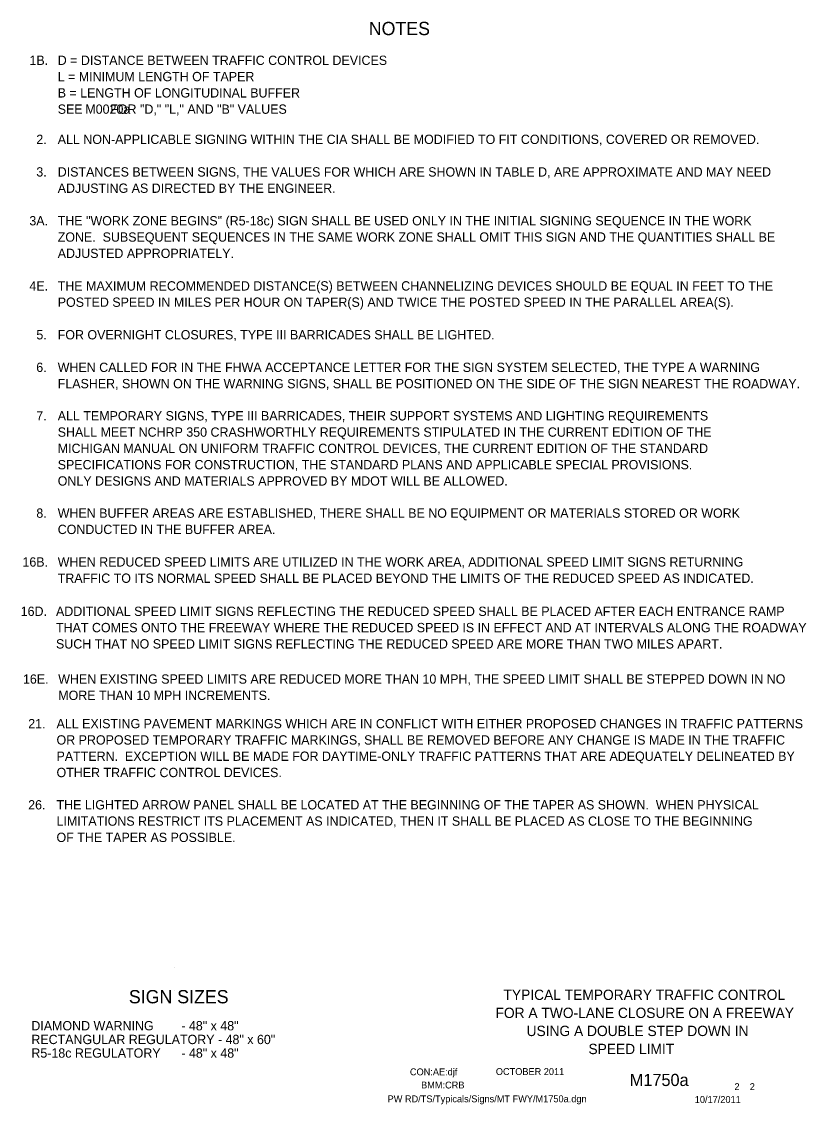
# Model space of a CAD drawing. Extents: x 16732 to 18478, y 5523 to 6928.
# Drawn here: x 17769 to 18478, y 5932 to 6909 of the extents above; entities that cross this region are included whole.
import ezdxf

# ---------------------------------------------------------------- set-up
doc = ezdxf.new("R2010")
doc.units = 0
for name, color, linetype in [('BORDER', 7, 'Continuous'), ('BORDER_SIGNAL_WO', 7, 'Continuous'), ('TYPICAL_TEXT_DIMEN_PR', 7, 'Continuous')]:
    doc.layers.add(name, color=color, linetype=linetype)

msp = doc.modelspace()

# ---------------------------------------------------------------- linework, layer by layer
at = {"layer": 'BORDER'}
for p, q in [((17907.48, 6055), (17907.48, 6055)), ((17907.48, 6035.02), (17907.48, 6035.02))]:
    msp.add_line(p, q, dxfattribs=at)

# ---------------------------------------------------------------- texts
for s, p in [('TYPICAL TEMPORARY TRAFFIC CONTROL', (18204.21, 6026.08)), ('FOR A TWO-LANE CLOSURE ON A FREEWAY', (18196.99, 6009.78)), ('USING A DOUBLE STEP DOWN IN', (18225.04, 5993.48)), ('SPEED LIMIT', (18280.92, 5977.18))]:
    msp.add_text(s, height=9.3, dxfattribs=at).set_placement(p)
at = {"layer": 'BORDER_SIGNAL_WO'}
for s, height, p in [('CON:AE:djf  ', 6.2, (18119.69, 5958.06)), ('    OCTOBER 2011', 6.2, (18188.08, 5958.34)), ('BMM:CRB', 6.2, (18129.81, 5946.17)), ('    M1750a   ', 11, (18301.86, 5948.38)), (' 2    2 ', 6.2, (18410.45, 5944.7)), ('PW RD/TS/Typicals/Signs/MT FWY/M1750a.dgn      ', 6.2, (18099.55, 5933.71)), ('10/17/2011', 6.2, (18376.93, 5933.13))]:
    msp.add_text(s, height=height, dxfattribs=at).set_placement(p)
at = {"layer": 'TYPICAL_TEXT_DIMEN_PR'}
for s, height, p in [('NOTES', 12, (18082.55, 6897)), ('1B.', 8.4, (17776.19, 6870.11)), ('D = DISTANCE BETWEEN TRAFFIC CONTROL DEVICES', 8.4, (17801.7, 6870.11)), ('L = MINIMUM LENGTH OF TAPER', 8.4, (17801.7, 6855.41)), ('B = LENGTH OF LONGITUDINAL BUFFER', 8.4, (17801.7, 6840.71)), ('SEE        FOR "D," "L," AND "B" VALUES', 8.4, (17801.7, 6826.01)), ('M0020a', 8.4, (17826.62, 6826.01)), ('2.', 8.4, (17782.39, 6798.75)), ('ALL NON-APPLICABLE SIGNING WITHIN THE CIA SHALL BE MODIFIED TO FIT CONDITIONS, COVERED OR REMOVED.', 8.4, (17801.7, 6798.75)), ('3.', 8.4, (17782.39, 6769.35)), ('DISTANCES BETWEEN SIGNS, THE VALUES FOR WHICH ARE SHOWN IN TABLE D, ARE APPROXIMATE AND MAY NEED', 8.4, (17801.7, 6769.35)), ('ADJUSTING AS DIRECTED BY THE ENGINEER.', 8.4, (17801.7, 6754.65)), ('THE "WORK ZONE BEGINS" (R5-18c) SIGN SHALL BE USED ONLY IN THE INITIAL SIGNING SEQUENCE IN THE WORK', 8.4, (17801.7, 6725.25)), ('3A.', 8.4, (17776.09, 6725.25)), ('ZONE.  SUBSEQUENT SEQUENCES IN THE SAME WORK ZONE SHALL OMIT THIS SIGN AND THE QUANTITIES SHALL BE', 8.4, (17801.7, 6710.55)), ('ADJUSTED APPROPRIATELY.', 8.4, (17801.7, 6695.85)), ('THE MAXIMUM RECOMMENDED DISTANCE(S) BETWEEN CHANNELIZING DEVICES SHOULD BE EQUAL IN FEET TO THE', 8.4, (17801.7, 6666.45)), ('4E.', 8.4, (17776.13, 6666.45)), ('POSTED SPEED IN MILES PER HOUR ON TAPER(S) AND TWICE THE POSTED SPEED IN THE PARALLEL AREA(S).', 8.4, (17801.7, 6651.75)), ('5.', 8.4, (17782.39, 6622.35)), ('FOR OVERNIGHT CLOSURES, TYPE III BARRICADES SHALL BE LIGHTED.', 8.4, (17801.7, 6622.35)), ('6.', 8.4, (17782.34, 6592.95)), ('WHEN CALLED FOR IN THE FHWA ACCEPTANCE LETTER FOR THE SIGN SYSTEM SELECTED, THE TYPE A WARNING ', 8.4, (17801.7, 6592.95)), ('FLASHER, SHOWN ON THE WARNING SIGNS, SHALL BE POSITIONED ON THE SIDE OF THE SIGN NEAREST THE ROADWAY.', 8.4, (17801.7, 6578.25)), ('7.', 8.4, (17782.34, 6549.16)), ('ALL TEMPORARY SIGNS, TYPE III BARRICADES, THEIR SUPPORT SYSTEMS AND LIGHTING REQUIREMENTS', 8.4, (17801.7, 6549.18)), ('SHALL MEET NCHRP 350 CRASHWORTHLY REQUIREMENTS STIPULATED IN THE CURRENT EDITION OF THE', 8.4, (17801.7, 6534.48)), ('MICHIGAN MANUAL ON UNIFORM TRAFFIC CONTROL DEVICES, THE CURRENT EDITION OF THE STANDARD', 8.4, (17801.7, 6519.78)), ('SPECIFICATIONS FOR CONSTRUCTION, THE STANDARD PLANS AND APPLICABLE SPECIAL PROVISIONS.', 8.4, (17801.7, 6505.08)), ('ONLY DESIGNS AND MATERIALS APPROVED BY MDOT WILL BE ALLOWED.', 8.4, (17801.7, 6490.38)), ('8.', 8.4, (17782.39, 6461.34)), ('WHEN BUFFER AREAS ARE ESTABLISHED, THERE SHALL BE NO EQUIPMENT OR MATERIALS STORED OR WORK     ', 8.4, (17801.7, 6461.34)), ('CONDUCTED IN THE BUFFER AREA.', 8.4, (17801.7, 6446.64)), ('16B.', 8.4, (17769.84, 6417.24)), ('WHEN REDUCED SPEED LIMITS ARE UTILIZED IN THE WORK AREA, ADDITIONAL SPEED LIMIT SIGNS RETURNING', 8.4, (17801.7, 6417.3)), ('TRAFFIC TO ITS NORMAL SPEED SHALL BE PLACED BEYOND THE LIMITS OF THE REDUCED SPEED AS INDICATED.', 8.4, (17801.7, 6402.6)), ('16D.', 8.4, (17768.27, 6372.72)), ('ADDITIONAL SPEED LIMIT SIGNS REFLECTING THE REDUCED SPEED SHALL BE PLACED AFTER EACH ENTRANCE RAMP', 8.4, (17800.14, 6372.72)), ('THAT COMES ONTO THE FREEWAY WHERE THE REDUCED SPEED IS IN EFFECT AND AT INTERVALS ALONG THE ROADWAY', 8.4, (17800.14, 6358.02)), ('SUCH THAT NO SPEED LIMIT SIGNS REFLECTING THE REDUCED SPEED ARE MORE THAN TWO MILES APART.', 8.4, (17800.14, 6343.32)), ('16E.', 8.4, (17770.3, 6311.56)), ('WHEN EXISTING SPEED LIMITS ARE REDUCED MORE THAN 10 MPH, THE SPEED LIMIT SHALL BE STEPPED DOWN IN NO', 8.4, (17802.16, 6311.56)), ('MORE THAN 10 MPH INCREMENTS.', 8.4, (17802.16, 6296.86)), ('21.', 8.4, (17775.06, 6271.31)), ('ALL EXISTING PAVEMENT MARKINGS WHICH ARE IN CONFLICT WITH EITHER PROPOSED CHANGES IN TRAFFIC PATTERNS', 8.4, (17800.62, 6271.31)), ('OR PROPOSED TEMPORARY TRAFFIC MARKINGS, SHALL BE REMOVED BEFORE ANY CHANGE IS MADE IN THE TRAFFIC', 8.4, (17800.62, 6256.61)), ('PATTERN.  EXCEPTION WILL BE MADE FOR DAYTIME-ONLY TRAFFIC PATTERNS THAT ARE ADEQUATELY DELINEATED BY', 8.4, (17800.62, 6241.91)), ('OTHER TRAFFIC CONTROL DEVICES.', 8.4, (17800.62, 6227.21)), ('26.', 8.4, (17775.01, 6198.04)), ('THE LIGHTED ARROW PANEL SHALL BE LOCATED AT THE BEGINNING OF THE TAPER AS SHOWN.  WHEN PHYSICAL', 8.4, (17800.62, 6198.04)), ('LIMITATIONS RESTRICT ITS PLACEMENT AS INDICATED, THEN IT SHALL BE PLACED AS CLOSE TO THE BEGINNING', 8.4, (17800.62, 6183.34)), ('OF THE TAPER AS POSSIBLE.', 8.4, (17800.62, 6168.64)), ('SIGN SIZES', 12, (17865.92, 6023.02)), ('DIAMOND WARNING        - 48" x 48"', 8.4, (17777.88, 5998.62)), ('RECTANGULAR REGULATORY - 48" x 60"', 8.4, (17777.88, 5986.22)), ('R5-18c REGULATORY      - 48" x 48"', 8.4, (17777.88, 5973.96))]:
    msp.add_text(s, height=height, dxfattribs=at).set_placement(p)

doc.saveas('drawing.dxf')
